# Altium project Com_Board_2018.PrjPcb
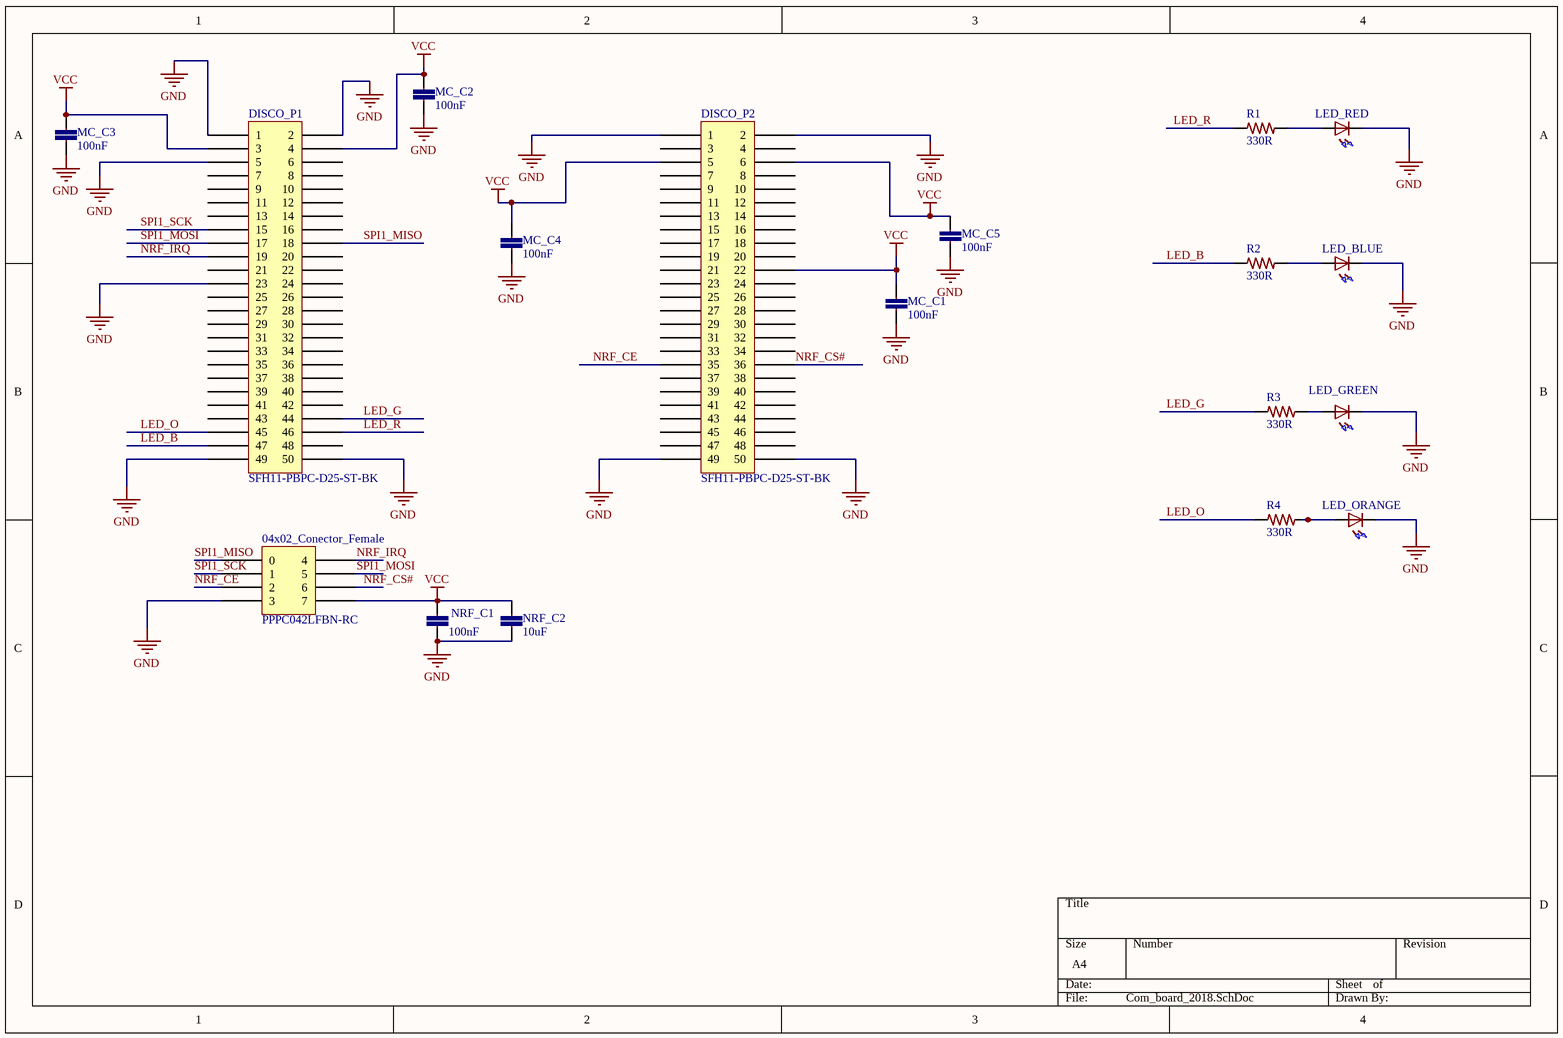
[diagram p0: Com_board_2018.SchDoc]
2 sheets, 34 parts. Net scope: hierarchical (ports join the sheet entries above them; power ports are global).
Board file: Com_Board_2018.PcbDoc
Sheets:
  Com_board_2018.SchDoc
  Periféricos.SchDoc

## Sheet Com_board_2018.SchDoc
size A4

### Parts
04x02_Conector_Female  PPPC042LFBN-RC  [04x02_Conector_Female]
DISCO_P1  SFH11-PBPC-D25-ST-BK  [25x02_Conector_Female]
DISCO_P2  SFH11-PBPC-D25-ST-BK  [25x02_Conector_Female]
LED_BLUE  LED  [LED-5MM-PCB]  (value not drawn)
LED_GREEN  LED  [LED-5MM-PCB]  (value not drawn)
LED_ORANGE  LED  [LED-5MM-PCB]  (value not drawn)
LED_RED  LED  [LED-5MM-PCB]  (value not drawn)
MC_C1  100nF  [0402-CAP]
MC_C2  100nF  [0402-CAP]
MC_C3  100nF  [0402-CAP]
MC_C4  100nF  [0402-CAP]
MC_C5  100nF  [0402-CAP]
NRF_C1  100nF  [0402-CAP]
NRF_C2  10uF  [0805-CAP]
R1  330R  [0402-RES-HD]
R2  330R  [0402-RES-HD]
R3  330R  [0402-RES-HD]
R4  330R  [0402-RES-HD]

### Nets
GND: 04x02_Conector_Female.3 DISCO_P1.1 DISCO_P1.2 DISCO_P1.5 DISCO_P1.23 DISCO_P1.49 DISCO_P1.50 DISCO_P2.1 DISCO_P2.2 DISCO_P2.49 DISCO_P2.50 LED_BLUE.1(K) LED_GREEN.1(K) LED_ORANGE.1(K) LED_RED.1(K) MC_C1.1 MC_C2.1 MC_C3.2 MC_C4.1 MC_C5.1 NRF_C1.2 NRF_C2.2
VCC: 04x02_Conector_Female.7 DISCO_P1.3 DISCO_P1.4 DISCO_P2.5 DISCO_P2.6 DISCO_P2.22 MC_C1.2 MC_C2.2 MC_C3.1 MC_C4.2 MC_C5.2 NRF_C1.1 NRF_C2.1
LED_B: DISCO_P1.47 R2.1
LED_G: DISCO_P1.44 R3.1
LED_O: DISCO_P1.45 R4.1
LED_R: DISCO_P1.46 R1.1
NRF_CE: 04x02_Conector_Female.2 DISCO_P2.35
NRF_CS#: 04x02_Conector_Female.6 DISCO_P2.36
NRF_IRQ: 04x02_Conector_Female.4 DISCO_P1.19
SPI1_MISO: 04x02_Conector_Female.0 DISCO_P1.18
SPI1_MOSI: 04x02_Conector_Female.5 DISCO_P1.17
SPI1_SCK: 04x02_Conector_Female.1 DISCO_P1.15
NetLED_BLUE_2: LED_BLUE.2(A) R2.2
NetLED_GREEN_2: LED_GREEN.2(A) R3.2
NetLED_ORANGE_2: LED_ORANGE.2(A) R4.2
NetLED_RED_2: LED_RED.2(A) R1.2

Not connected (* = marked no-connect by the designer): DISCO_P1 6 7 8 9 10 11 12 13 14 16 20 21 22 24 25 26 27 28 29 30 31 32 33 34 35 36 37 38 39 40 41 42 43 48; DISCO_P2 3 4 7 8 9 10 11 12 13 14 15 16 17 18 19 20 21 23 24 25 26 27 28 29 30 31 32 33 34 37 38 39 40 41 42 43 44 45 46 47 48

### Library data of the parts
04x02_Conector_Female = 04x02_Conector_Female: 8 Position Header Connector 0.100" (2.54mm) Through Hole Gold
DISCO_P1 DISCO_P2 = 25x02_Conector_Female: 50 Position Header Connector 0.100" (2.54mm) Through Hole Gold
LED_BLUE LED_GREEN LED_ORANGE LED_RED = LED-5MM-3: LED 5MM PTH
MC_C1-MC_C5 NRF_C1 = CC0402-100nF-A.12: CAP CER 0.1UF 10V 20% X5R 0402; Part No: VJ0402V104ZXQPBC; Cod EMS: 05.281.006.133; Value: 100n
NRF_C2 = CC0806-10uF-25V-1: CAP CER 10UF 25V X5R 0805; Part No: GRM21BR61E106KA73L; Cod EMS: 05.281.019.590
R1-R4 = R0402-330R-7: RES 330 OHM 1/10W 1% 0402 SMD; Part No: ERJ-2RKF3300X; Cod EMS: 05.280.029.506; Value: 330; Family Description: RESISTOR FILME ESPESSO 10R-1M / 1/10W / 1% / 0402. P/N: ERJ-2RKF....X – PANASONIC ELECTRONIC COMPONENTS.

## Sheet Periféricos.SchDoc
size A4
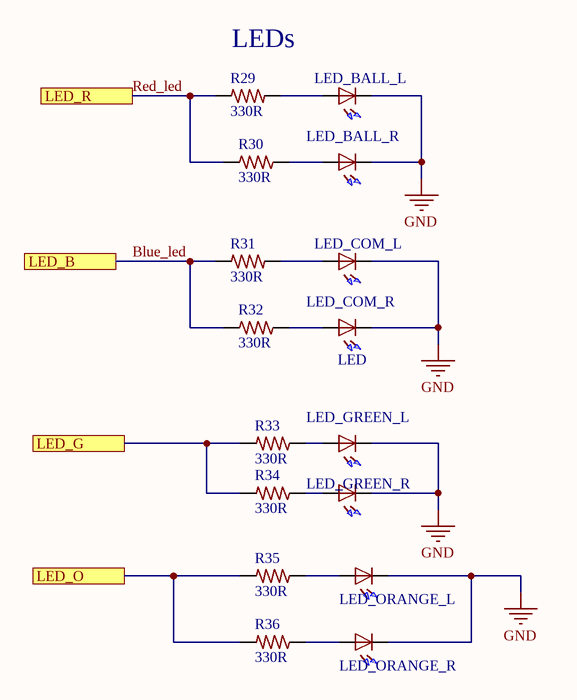
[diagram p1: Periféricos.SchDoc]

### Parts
LED_BALL_L  LED  [LED-5MM-PCB]  (value not drawn)
LED_BALL_R  LED  [LED-5MM-PCB]  (value not drawn)
LED_COM_L  LED  [LED-5MM-PCB]  (value not drawn)
LED_COM_R  LED  [LED-5MM-PCB]
LED_GREEN_L  LED  [LED-5MM-PCB]  (value not drawn)
LED_GREEN_R  LED  [LED-5MM-PCB]  (value not drawn)
LED_ORANGE_L  LED  [LED-5MM-PCB]  (value not drawn)
LED_ORANGE_R  LED  [LED-5MM-PCB]  (value not drawn)
R29  330R  [0402-RES-HD]
R30  330R  [0402-RES-HD]
R31  330R  [0402-RES-HD]
R32  330R  [0402-RES-HD]
R33  330R  [0402-RES-HD]
R34  330R  [0402-RES-HD]
R35  330R  [0402-RES-HD]
R36  330R  [0402-RES-HD]

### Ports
LED_B, LED_G, LED_O, LED_R

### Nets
GND: LED_BALL_L.1(K) LED_BALL_R.1(K) LED_COM_L.1(K) LED_COM_R.1(K) LED_GREEN_L.1(K) LED_GREEN_R.1(K) LED_ORANGE_L.1(K) LED_ORANGE_R.1(K)
Blue_led: R31.1 R32.1 ; port LED_B
Red_led: R29.1 R30.1 ; port LED_R
NetLED_BALL_L_2: LED_BALL_L.2(A) R29.2
NetLED_BALL_R_2: LED_BALL_R.2(A) R30.2
NetLED_COM_L_2: LED_COM_L.2(A) R31.2
NetLED_COM_R_2: LED_COM_R.2(A) R32.2
NetLED_GREEN_L_2: LED_GREEN_L.2(A) R33.2
NetLED_GREEN_R_2: LED_GREEN_R.2(A) R34.2
NetLED_ORANGE_L_2: LED_ORANGE_L.2(A) R35.2
NetLED_ORANGE_R_2: LED_ORANGE_R.2(A) R36.2
NetR33_1: R33.1 R34.1 ; port LED_G
NetR35_1: R35.1 R36.1 ; port LED_O

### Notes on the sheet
- (near R29) LEDs

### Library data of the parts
LED_BALL_L LED_BALL_R LED_COM_L LED_COM_R LED_GREEN_L LED_GREEN_R LED_ORANGE_L LED_ORANGE_R = LED-5MM-3: LED 5MM PTH
R29-R36 = R0402-330R-7: as R1 on sheet Com_board_2018

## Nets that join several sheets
GND: Com_board_2018 (22 pins), Periféricos (8 pins)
